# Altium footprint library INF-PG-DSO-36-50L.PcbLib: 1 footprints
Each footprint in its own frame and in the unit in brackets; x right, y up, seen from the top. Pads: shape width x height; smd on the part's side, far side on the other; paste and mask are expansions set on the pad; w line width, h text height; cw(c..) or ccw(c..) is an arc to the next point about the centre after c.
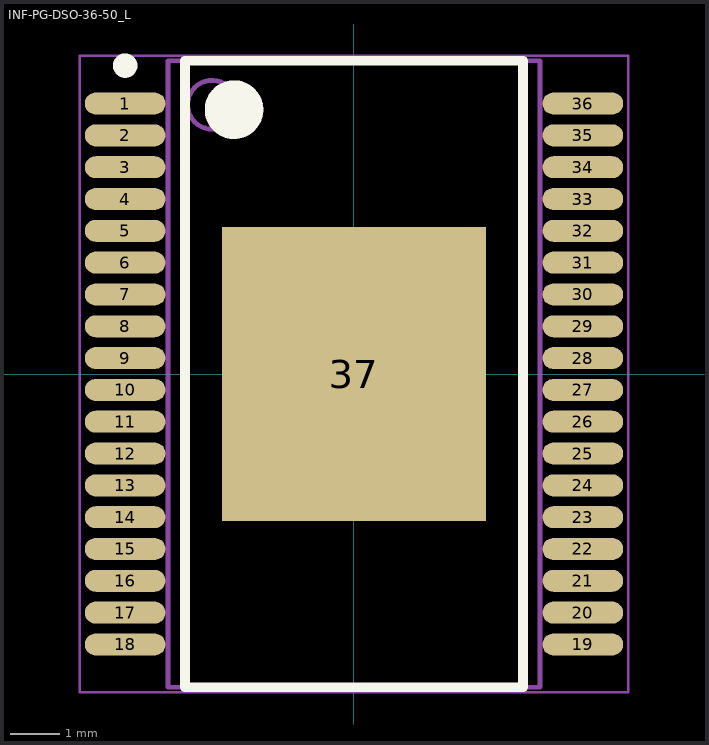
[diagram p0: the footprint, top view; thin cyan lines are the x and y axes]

## INF-PG-DSO-36-50_L [mm] "SOP, 36-Leads, Body 12.7x7.5mm, Pitch 0.65mm, Thermal Pad 6000x5400mm, IPC High Density"
height 2.55
pads (37):
  oval 1.65x0.45 smd: 1(-4.675,5.525) 2(-4.675,4.875) 3(-4.675,4.225) 4(-4.675,3.575) 5(-4.675,2.925) 6(-4.675,2.275) 7(-4.675,1.625) 8(-4.675,0.975) 9(-4.675,0.325) 10(-4.675,-0.325) 11(-4.675,-0.975) 12(-4.675,-1.625) 13(-4.675,-2.275) 14(-4.675,-2.925) 15(-4.675,-3.575) 16(-4.675,-4.225) 17(-4.675,-4.875) 18(-4.675,-5.525) 19(4.675,-5.525) 20(4.675,-4.875) 21(4.675,-4.225) 22(4.675,-3.575) 23(4.675,-2.925) 24(4.675,-2.275) 25(4.675,-1.625) 26(4.675,-0.975) 27(4.675,-0.325) 28(4.675,0.325) 29(4.675,0.975) 30(4.675,1.625) 31(4.675,2.275) 32(4.675,2.925) 33(4.675,3.575) 34(4.675,4.225) 35(4.675,4.875) 36(4.675,5.525)
  rect 5.4x6 smd: 37(0,0)
Top Overlay:
  circle w0.25: c-4.675,6.3 r0.125
  circle w0.6: c-2.45,5.4 r0.3
  lines w0.2: -3.45,-6.4 -3.45,6.4 3.45,6.4 3.45,-6.4 -3.45,-6.4
Mechanical 13:
  circle w0.1: c-2.9,5.5 r0.5
  lines w0.1: -3.8,-6.4 -3.8,6.4 3.8,6.4 3.8,-6.4 -3.8,-6.4
Mechanical 15:
  lines w0.05: -5.6,-6.5 -5.6,6.5 5.6,6.5 5.6,-6.5 -5.6,-6.5
  lines w0.1: -0.5,0 0.5,0 ; 0,-0.5 0,0.5
3D body: height 2.55, standoff 0, extent -3.8,-6.4 3.8,6.4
